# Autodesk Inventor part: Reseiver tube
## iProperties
Created: 2006-04
Part Number: Reseiver tube
Document SubType Name: Modeling
Designer: Калинин
Author: Калинин
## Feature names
1. Выдавливание1 [Extrusion]
2. Выдавливание2 [Extrusion]
3. Выдавливание3 [Extrusion]
4. Выдавливание4 [Extrusion]
5. Выдавливание5 [Extrusion]
6. Выдавливание6 [Extrusion]
7. Круговой массив1 [Circular Pattern]
8. Выдавливание7 [Extrusion]
9. Выдавливание8 [Extrusion]
10. Сопряжение1 [Fillet]
11. Сопряжение2 [Fillet]
12. Сопряжение3 [Fillet]
13. Сопряжение4 [Fillet]
14. Сопряжение5 [Fillet]
15. Сопряжение6 [Fillet]
16. Сопряжение7 [Fillet]
17. Выдавливание9 [Extrusion]
18. Сопряжение8 [Fillet]
19. Сопряжение9 [Fillet]
